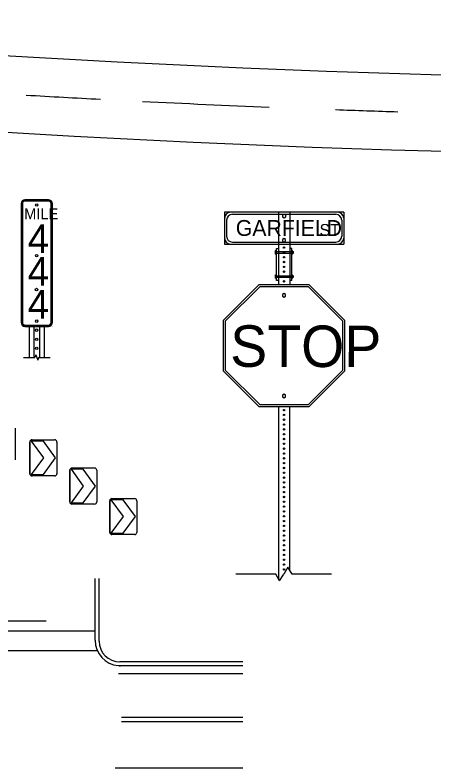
# Model space of a CAD drawing. Extents: x 49991.4 to 50021, y 49987.6 to 50011.4.
# Drawn here: x 50002.261 to 50003.356, y 50006.027 to 50007.995 of the extents above; entities that cross this region are included whole.
import ezdxf

# ---------------------------------------------------------------- set-up
doc = ezdxf.new("R2010")
doc.units = 0
for name, color, linetype in [('Level 1', 7, 'Continuous'), ('Level 10', 7, 'Continuous'), ('Level 2', 7, 'Continuous'), ('Level 4', 7, 'Continuous'), ('Level 6', 7, 'Continuous')]:
    doc.layers.add(name, color=color, linetype=linetype)

msp = doc.modelspace()

# ---------------------------------------------------------------- linework, layer by layer
at = {"layer": 'Level 1'}
for p, q in [((50002.2769, 50007.502), (50002.2769, 50007.1916)), ((50002.2786, 50007.502), (50002.2786, 50007.1916)), ((50002.2803, 50007.502), (50002.2803, 50007.1916)), ((50002.3484, 50007.5122), (50002.2871, 50007.5122)), ((50002.3484, 50007.5105), (50002.2871, 50007.5105)), ((50002.3484, 50007.5088), (50002.2871, 50007.5088)), ((50002.3552, 50007.1916), (50002.3552, 50007.502)), ((50002.3569, 50007.1916), (50002.3569, 50007.502)), ((50002.3586, 50007.1916), (50002.3586, 50007.502)), ((50002.809, 50007.4795), (50002.809, 50007.3964)), ((50003.1204, 50007.4795), (50002.809, 50007.4795)), ((50002.8297, 50007.4742), (50003.0996, 50007.4742)), ((50003.1204, 50007.4795), (50003.1204, 50007.3964)), ((50002.8142, 50007.4587), (50002.8142, 50007.4172)), ((50003.1152, 50007.4587), (50003.1152, 50007.4172)), ((50002.809, 50007.3964), (50003.1204, 50007.3964)), ((50002.8297, 50007.4016), (50003.0996, 50007.4016)), ((50002.9499, 50007.3964), (50002.9499, 50007.2899)), ((50002.9792, 50007.3964), (50002.9792, 50007.2899)), ((50002.9423, 50007.37), (50002.9423, 50007.3794)), ((50002.9423, 50007.3794), (50002.9443, 50007.3794)), ((50002.9423, 50007.3776), (50002.9443, 50007.3776)), ((50002.9443, 50007.3016), (50002.9443, 50007.3847)), ((50002.9443, 50007.3847), (50002.9499, 50007.3847)), ((50002.9499, 50007.3847), (50002.9499, 50007.3016)), ((50002.9849, 50007.3847), (50002.9792, 50007.3847)), ((50002.9792, 50007.3847), (50002.9792, 50007.3016)), ((50002.9849, 50007.3016), (50002.9849, 50007.3847)), ((50002.9849, 50007.3794), (50002.9868, 50007.3794)), ((50002.9849, 50007.3776), (50002.9868, 50007.3776)), ((50002.9868, 50007.37), (50002.9868, 50007.3794)), ((50002.9868, 50007.3766), (50002.9889, 50007.3766)), ((50002.9889, 50007.3729), (50002.9889, 50007.3766)), ((50002.9423, 50007.3719), (50002.9443, 50007.3719)), ((50002.9423, 50007.37), (50002.9443, 50007.37)), ((50002.9849, 50007.3719), (50002.9868, 50007.3719)), ((50002.9849, 50007.37), (50002.9868, 50007.37)), ((50002.9868, 50007.3729), (50002.9889, 50007.3729)), ((50002.9423, 50007.307), (50002.9423, 50007.3163)), ((50002.9423, 50007.3163), (50002.9443, 50007.3163)), ((50002.9849, 50007.3163), (50002.9868, 50007.3163)), ((50002.9868, 50007.307), (50002.9868, 50007.3163)), ((50002.9423, 50007.3145), (50002.9443, 50007.3145)), ((50002.9423, 50007.3088), (50002.9443, 50007.3088)), ((50002.9423, 50007.307), (50002.9443, 50007.307)), ((50002.9499, 50007.3016), (50002.9443, 50007.3016)), ((50002.9849, 50007.3016), (50002.9792, 50007.3016)), ((50002.9849, 50007.3145), (50002.9868, 50007.3145)), ((50002.9849, 50007.3088), (50002.9868, 50007.3088)), ((50002.9849, 50007.307), (50002.9868, 50007.307)), ((50002.9868, 50007.3135), (50002.9889, 50007.3135)), ((50002.9868, 50007.3097), (50002.9889, 50007.3097)), ((50002.9889, 50007.3097), (50002.9889, 50007.3135)), ((50002.2871, 50007.1848), (50002.3484, 50007.1848)), ((50002.2871, 50007.1831), (50002.3484, 50007.1831)), ((50002.2871, 50007.1814), (50002.3484, 50007.1814)), ((50002.2981, 50007.1814), (50002.2981, 50007.1003)), ((50002.3098, 50007.1814), (50002.3098, 50007.1003)), ((50002.3252, 50007.1814), (50002.3252, 50007.1003)), ((50002.3374, 50007.1814), (50002.3374, 50007.1003)), ((50002.9498, 50006.9717), (50002.9498, 50006.521)), ((50002.979, 50006.9717), (50002.979, 50006.5444)), ((50002.2611, 50006.9153), (50002.2611, 50006.8326)), ((50002.3055, 50006.8848), (50002.3645, 50006.8848)), ((50002.2996, 50006.7962), (50002.2996, 50006.8789)), ((50002.2996, 50006.7962), (50002.2996, 50006.8789)), ((50002.2996, 50006.8789), (50002.2996, 50006.7962)), ((50002.3351, 50006.8814), (50002.303, 50006.8814)), ((50002.303, 50006.8814), (50002.3351, 50006.8376)), ((50002.3671, 50006.8376), (50002.3351, 50006.8814)), ((50002.3705, 50006.8789), (50002.3705, 50006.7962)), ((50002.3351, 50006.8376), (50002.303, 50006.7938)), ((50002.3351, 50006.7938), (50002.3671, 50006.8376)), ((50002.404, 50006.7225), (50002.404, 50006.8052)), ((50002.404, 50006.7225), (50002.404, 50006.8052)), ((50002.404, 50006.8052), (50002.404, 50006.7225)), ((50002.4395, 50006.8077), (50002.4074, 50006.8077)), ((50002.4074, 50006.8077), (50002.4395, 50006.7639)), ((50002.4099, 50006.8112), (50002.4689, 50006.8112)), ((50002.4715, 50006.7639), (50002.4395, 50006.8077)), ((50002.4749, 50006.8052), (50002.4749, 50006.7225)), ((50002.303, 50006.7938), (50002.3351, 50006.7938)), ((50002.3645, 50006.7903), (50002.3055, 50006.7903)), ((50002.4395, 50006.7639), (50002.4074, 50006.7201)), ((50002.4395, 50006.7201), (50002.4715, 50006.7639)), ((50002.5085, 50006.6428), (50002.5085, 50006.7255)), ((50002.5085, 50006.6428), (50002.5085, 50006.7255)), ((50002.5085, 50006.7255), (50002.5085, 50006.6428)), ((50002.5439, 50006.728), (50002.5119, 50006.728)), ((50002.5119, 50006.728), (50002.5439, 50006.6842)), ((50002.5144, 50006.7314), (50002.5734, 50006.7314)), ((50002.576, 50006.6842), (50002.5439, 50006.728)), ((50002.5794, 50006.7255), (50002.5794, 50006.6428)), ((50002.4074, 50006.7201), (50002.4395, 50006.7201)), ((50002.4689, 50006.7167), (50002.4099, 50006.7167)), ((50002.5439, 50006.6842), (50002.5119, 50006.6404)), ((50002.5439, 50006.6404), (50002.576, 50006.6842)), ((50002.5119, 50006.6404), (50002.5439, 50006.6404)), ((50002.5734, 50006.6369), (50002.5144, 50006.6369)), ((50002.4706, 50006.3607), (50002.4706, 50006.5226)), ((50002.481, 50006.3589), (50002.481, 50006.5226)), ((50002.8564, 50006.2943), (50002.5318, 50006.2943)), ((50002.8564, 50006.3045), (50002.5354, 50006.3045)), ((50002.8564, 50006.2731), (50002.5318, 50006.2731)), ((50002.8564, 50006.1586), (50002.539, 50006.1586)), ((50002.8564, 50006.1477), (50002.539, 50006.1477)), ((50002.5231, 50006.0271), (50002.8564, 50006.0271))]:
    msp.add_line(p, q, dxfattribs=at)
for points in [[(50002.9606, 50007.4717), (50002.9606, 50007.4672), (50002.9646, 50007.4648), (50002.9687, 50007.4672), (50002.9687, 50007.4717), (50002.9646, 50007.4741)], [(50002.9606, 50007.4087), (50002.9606, 50007.404), (50002.9646, 50007.4017), (50002.9686, 50007.404), (50002.9686, 50007.4087), (50002.9646, 50007.4109)], [(50003.1235, 50007.0649), (50003.1235, 50007.1967), (50003.0303, 50007.2899), (50002.8985, 50007.2899), (50002.8053, 50007.1967), (50002.8053, 50007.0649), (50002.8985, 50006.9717), (50003.0303, 50006.9717)], [(50003.1182, 50007.0671), (50003.1182, 50007.1945), (50003.0281, 50007.2846), (50002.9007, 50007.2846), (50002.8106, 50007.1945), (50002.8106, 50007.0671), (50002.9007, 50006.977), (50003.0281, 50006.977)], [(50002.9605, 50007.2645), (50002.9605, 50007.2599), (50002.9645, 50007.2575), (50002.9685, 50007.2599), (50002.9685, 50007.2645), (50002.9645, 50007.2669)], [(50002.9603, 50007.0017), (50002.9603, 50006.9971), (50002.9643, 50006.9947), (50002.9684, 50006.9971), (50002.9684, 50007.0017), (50002.9643, 50007.004)]]:
    msp.add_lwpolyline(points, close=True, dxfattribs=at)
for centre, radius in [((50002.3178, 50007.4987), 0.00327), ((50002.9645, 50007.3874), 0.00185), ((50002.9645, 50007.3747), 0.00185), ((50002.3175, 50007.3661), 0.00327), ((50002.9645, 50007.3621), 0.00185), ((50002.9645, 50007.3495), 0.00185), ((50002.9645, 50007.3369), 0.00185), ((50002.9645, 50007.3242), 0.00185), ((50002.9645, 50007.3116), 0.00185), ((50002.9645, 50007.299), 0.00185), ((50002.3171, 50007.2775), 0.00327), ((50002.3178, 50007.1949), 0.00327), ((50002.3176, 50007.1713), 0.00327), ((50002.3178, 50007.1476), 0.00327), ((50002.3178, 50007.1239), 0.00327), ((50002.9644, 50006.9626), 0.00185), ((50002.9644, 50006.95), 0.00185), ((50002.9644, 50006.9374), 0.00185), ((50002.9644, 50006.9248), 0.00185), ((50002.9644, 50006.9121), 0.00185), ((50002.9644, 50006.8995), 0.00185), ((50002.9644, 50006.8869), 0.00185), ((50002.9644, 50006.8743), 0.00185), ((50002.9644, 50006.8616), 0.00185), ((50002.9644, 50006.849), 0.00185), ((50002.9644, 50006.8364), 0.00185), ((50002.9644, 50006.8238), 0.00185), ((50002.9644, 50006.8112), 0.00185), ((50002.9644, 50006.7985), 0.00185), ((50002.9644, 50006.7859), 0.00185), ((50002.9644, 50006.7733), 0.00185), ((50002.9644, 50006.7607), 0.00185), ((50002.9644, 50006.748), 0.00185), ((50002.9644, 50006.7354), 0.00185), ((50002.9644, 50006.7228), 0.00185), ((50002.9644, 50006.7102), 0.00185), ((50002.9644, 50006.6976), 0.00185), ((50002.9644, 50006.6849), 0.00185), ((50002.9644, 50006.6723), 0.00185), ((50002.9644, 50006.6597), 0.00185), ((50002.9644, 50006.6471), 0.00185), ((50002.9644, 50006.6344), 0.00185), ((50002.9644, 50006.6218), 0.00185), ((50002.9644, 50006.6092), 0.00185), ((50002.9644, 50006.5966), 0.00185), ((50002.9644, 50006.584), 0.00185), ((50002.9644, 50006.5713), 0.00185), ((50002.9644, 50006.5587), 0.00185), ((50002.9644, 50006.5461), 0.00185)]:
    msp.add_circle(centre, radius, dxfattribs=at)
for centre, radius, start, end in [((50004.3941, 50043.9715), 36.1468, 264.4363, 275.54852), ((50004.3941, 50043.9715), 36.3468, 264.75129, 275.22467), ((50004.3941, 50043.9715), 36.2468, 266.67245, 266.98033), ((50004.3941, 50043.9715), 36.2468, 267.15326, 267.67801), ((50004.3941, 50043.9715), 36.2468, 267.95265, 268.21045), ((50002.2872, 50007.502), 0.0102, 90, 180), ((50002.2872, 50007.502), 0.00851, 90, 180), ((50002.2872, 50007.502), 0.00681, 90, 180), ((50002.3484, 50007.502), 0.0102, 0, 90), ((50002.3484, 50007.502), 0.00851, 0, 90), ((50002.3484, 50007.502), 0.00681, 0, 90), ((50002.8245, 50007.4639), 0.0156, 90, 180), ((50002.8297, 50007.4587), 0.0156, 90, 180), ((50003.0996, 50007.4587), 0.0156, 0, 90), ((50003.1048, 50007.4639), 0.0156, 0, 90), ((50002.8297, 50007.4172), 0.0156, 180, 270), ((50003.0996, 50007.4172), 0.0156, 270, 360), ((50002.8245, 50007.412), 0.0156, 180, 270), ((50003.1048, 50007.412), 0.0156, 270, 360), ((50002.2872, 50007.1916), 0.0102, 180, 270), ((50002.2872, 50007.1916), 0.00851, 180, 270), ((50002.2872, 50007.1916), 0.00681, 180, 270), ((50002.3484, 50007.1916), 0.0102, 270, 360), ((50002.3484, 50007.1916), 0.00851, 270, 360), ((50002.3484, 50007.1916), 0.00681, 270, 360), ((50002.3055, 50006.8789), 0.00591, 90, 180), ((50002.3646, 50006.8789), 0.00591, 0, 90), ((50002.4099, 50006.8052), 0.00591, 90, 180), ((50002.469, 50006.8052), 0.00591, 0, 90), ((50002.3055, 50006.7962), 0.00591, 180, 270), ((50002.3646, 50006.7962), 0.00591, 270, 0), ((50002.5144, 50006.7255), 0.00591, 90, 180), ((50002.5735, 50006.7255), 0.00591, 0, 90), ((50002.4099, 50006.7226), 0.00591, 180, 270), ((50002.469, 50006.7226), 0.00591, 270, 0), ((50002.5144, 50006.6428), 0.00591, 180, 270), ((50002.5735, 50006.6428), 0.00591, 270, 0), ((50002.5371, 50006.3608), 0.0665, 180, 265.0709), ((50002.5353, 50006.3589), 0.0545, 180, 270), ((50002.5371, 50006.3608), 0.0665, 265.0709, 270)]:
    msp.add_arc(centre, radius, start, end, dxfattribs=at)
at = {"layer": 'Level 10'}
for p, q in [((50002.3427, 50006.4111), (50002.2154, 50006.4111)), ((50002.4706, 50006.3843), (50002.2154, 50006.3843)), ((50002.4762, 50006.3334), (50002.2093, 50006.3334))]:
    msp.add_line(p, q, dxfattribs=at)
at = {"layer": 'Level 2'}
for p, q in [((50002.3583, 50007.1816), (50002.3583, 50007.1816)), ((50002.3586, 50007.1814), (50002.3586, 50007.1814))]:
    msp.add_line(p, q, dxfattribs=at)
at = {"layer": 'Level 4'}
for p, q in [((50002.9499, 50007.4795), (50002.9499, 50007.3964)), ((50002.9792, 50007.4794), (50002.9792, 50007.3964)), ((50002.9443, 50007.3766), (50002.9849, 50007.3766)), ((50002.9443, 50007.3729), (50002.9849, 50007.3729)), ((50002.9443, 50007.3135), (50002.9849, 50007.3135)), ((50002.9443, 50007.3097), (50002.9849, 50007.3097))]:
    msp.add_line(p, q, dxfattribs=at)
at = {"layer": 'Level 6'}
for p, q in [((50002.2828, 50007.1003), (50002.3128, 50007.1003)), ((50002.3153, 50007.1073), (50002.3128, 50007.1003)), ((50002.3153, 50007.1073), (50002.3178, 50007.1003)), ((50002.3178, 50007.1003), (50002.3203, 50007.0932)), ((50002.3228, 50007.1003), (50002.3203, 50007.0932)), ((50002.3228, 50007.1003), (50002.3528, 50007.1003)), ((50002.9747, 50006.5521), (50002.9634, 50006.5336)), ((50002.9852, 50006.5336), (50002.9747, 50006.5521)), ((50002.9426, 50006.5336), (50002.8382, 50006.5336)), ((50002.9526, 50006.5159), (50002.9426, 50006.5336)), ((50002.9526, 50006.5158), (50002.9634, 50006.5336)), ((50003.0888, 50006.5336), (50002.9852, 50006.5336))]:
    msp.add_line(p, q, dxfattribs=at)

# ---------------------------------------------------------------- texts
at = {"layer": 'Level 1'}
for s, height, p in [('MILE', 0.02859, (50002.2848, 50007.4612)), ('4', 0.0749, (50002.2941, 50007.3727)), ('4', 0.0749, (50002.2941, 50007.2876)), ('4', 0.0749, (50002.2941, 50007.2018))]:
    msp.add_text(s, height=height, dxfattribs=at).set_placement(p)
for s, height, rotation, p in [('GARFIELD', 0.04152, 0.0001, (50002.8382, 50007.4177)), ('ST', 0.03114, 359.999, (50003.0572, 50007.4177)), ('STOP', 0.1085, 359.8333, (50002.8235, 50007.0757))]:
    msp.add_text(s, height=height, rotation=rotation, dxfattribs=at).set_placement(p)

doc.saveas('drawing.dxf')
